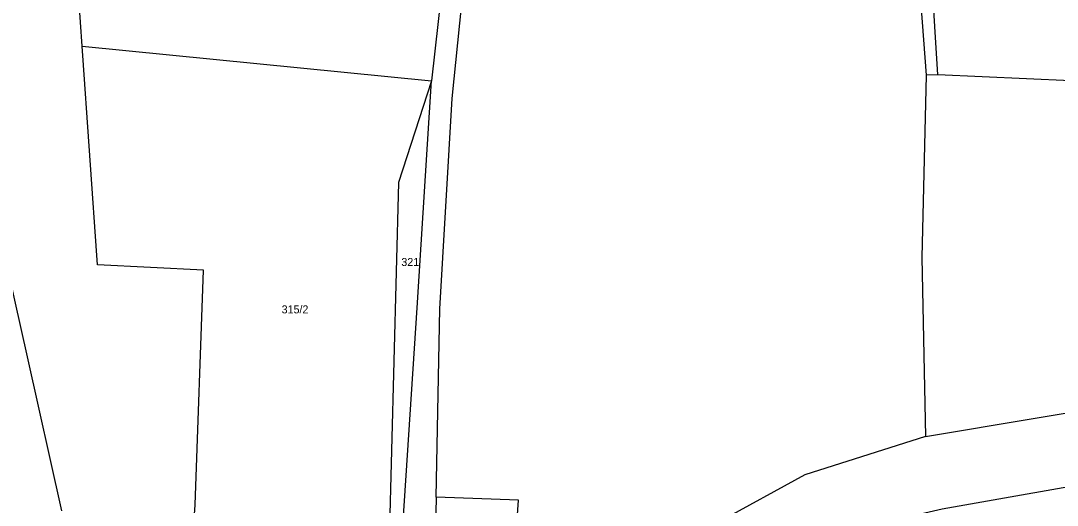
# Model space of a CAD drawing. Extents: x -887272 to -877616, y -1026687 to -1019819.
# Drawn here: x -878781.4 to -878561.2, y -1022300.1 to -1022197.1 of the extents above; entities that cross this region are included whole.
import ezdxf

# ---------------------------------------------------------------- set-up
doc = ezdxf.new("R2010")
doc.units = 0
doc.layers.add('Hranice parcel', color=7, linetype='Continuous')
doc.layers.add('Parcelní čísla', color=7, linetype='Continuous')

msp = doc.modelspace()

# ---------------------------------------------------------------- linework, layer by layer
at = {"layer": 'Hranice parcel'}
for p, q in [((-878768.4, -1022202.48), (-878694.18, -1022209.89)), ((-878586.62, -1022208.6), (-878589.06, -1022208.62)), ((-878693.21, -1022298.36), (-878693.64, -1022324.29))]:
    msp.add_line(p, q, dxfattribs=at)
for points in [[(-878693.21, -1022298.36), (-878692.4, -1022258.3), (-878689.78, -1022213.59), (-878684.22, -1022158.54), (-878682.26, -1022103.14), (-878673.47, -1022036.72), (-878669.09, -1021992.24), (-878665.96, -1021938.56), (-878659.56, -1021864.21), (-878651.12, -1021830.64), (-878647.4, -1021802.19), (-878644.62, -1021778.59), (-878640.81, -1021757.55), (-878636.77, -1021734.3), (-878635.51, -1021701.34), (-878633.33, -1021667.69), (-878631.59, -1021625.86), (-878630.9, -1021607.55), (-878630.94, -1021582.96), (-878627.58, -1021573.01)], [(-878586.62, -1022208.6), (-878589.91, -1022154.89), (-878571.07, -1022003.66), (-878565.03, -1021980.86), (-878569.45, -1021980.25), (-878574.67, -1022003.38), (-878593.2, -1022154.07), (-878589.06, -1022208.62)], [(-878796.62, -1022014.79), (-878799.81, -1022095.23), (-878802.22, -1022134.81), (-878802.77, -1022161.7), (-878801.33, -1022180.04), (-878788.12, -1022233), (-878780.08, -1022268.54), (-878772.79, -1022301.21)], [(-878768.4, -1022202.48), (-878769.12, -1022192.22), (-878768.28, -1022125.33), (-878761.32, -1022093.01), (-878746.55, -1022089.12), (-878733.6, -1022035.04)], [(-878676.69, -1022035.16), (-878688.26, -1022101.67), (-878688.42, -1022158.68), (-878694.18, -1022209.89)], [(-878745.08, -1022310.27), (-878744.37, -1022299.96), (-878742.62, -1022250.12), (-878765.12, -1022248.99), (-878768.4, -1022202.48)], [(-878589.06, -1022208.62), (-878590, -1022247.37), (-878589.21, -1022285.43)], [(-878461.63, -1022254.79), (-878477.42, -1022247.38), (-878501.8, -1022232.02), (-878527.45, -1022220.17), (-878558.36, -1022209.87), (-878586.62, -1022208.6)], [(-878694.18, -1022209.89), (-878701.22, -1022231.48), (-878703.15, -1022307.41), (-878700.45, -1022307.74)], [(-878700.45, -1022307.74), (-878697.19, -1022258.12), (-878694.18, -1022209.89)], [(-878589.21, -1022285.43), (-878519.72, -1022273.83), (-878469.66, -1022258.46), (-878461.63, -1022254.79)], [(-878466.42, -1022273.02), (-878507.75, -1022287.12), (-878585.67, -1022300.91), (-878609.56, -1022306.45)], [(-878589.21, -1022285.43), (-878614.84, -1022293.57), (-878633.22, -1022303.64), (-878648.06, -1022314.55), (-878665.5, -1022328.26), (-878678.8, -1022344.27)], [(-878678.8, -1022344.27), (-878675.7, -1022298.99), (-878693.21, -1022298.36)]]:
    msp.add_lwpolyline(points, dxfattribs=at)

# ---------------------------------------------------------------- texts
at = {"layer": 'Parcelní čísla'}
for s, p in [('321', (-878700.59, -1022249.21)), ('315/2', (-878726.02, -1022259.28))]:
    msp.add_text(s, height=1.7, dxfattribs=at).set_placement(p)

doc.saveas('drawing.dxf')
